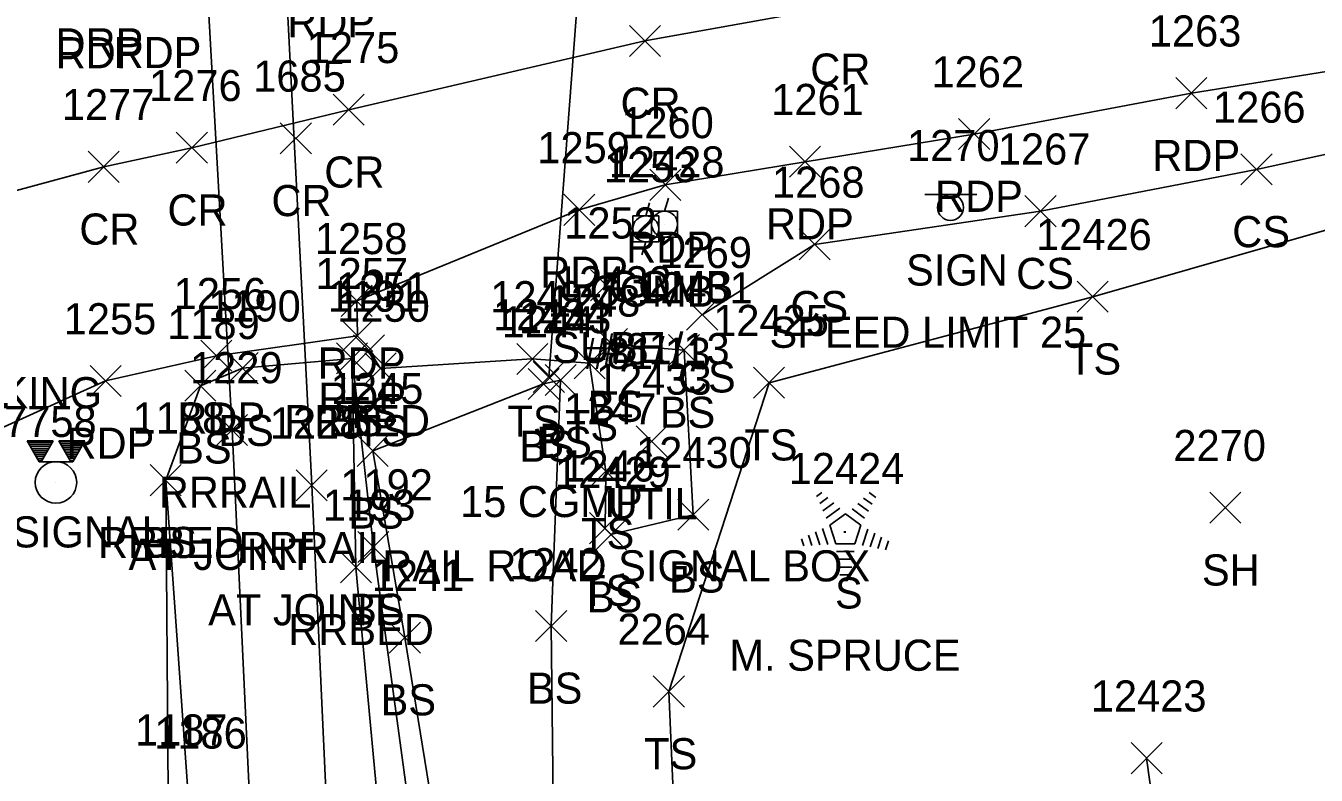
# Model space of a CAD drawing. Extents: x 1769141 to 1770817, y 735471 to 742405.
# Drawn here: x 1770150.6 to 1770233.5, y 741062.5 to 741110.6 of the extents above; entities that cross this region are included whole.
import ezdxf

# ---------------------------------------------------------------- set-up
doc = ezdxf.new("R2010")
doc.units = 0
for name, color, linetype in [('D_A', 7, 'Continuous'), ('D_C', 7, 'Continuous'), ('D_I', 7, 'Continuous'), ('D_TIC', 7, 'Continuous'), ('DCP', 7, 'Continuous'), ('L_A', 7, 'Continuous'), ('L_C', 7, 'Continuous'), ('L_I', 7, 'Continuous'), ('L_TIC', 7, 'Continuous'), ('LDEFAULT', 7, 'Continuous'), ('LELB', 7, 'Continuous'), ('LTC', 7, 'Continuous'), ('P_A', 7, 'Continuous'), ('P_I', 7, 'Continuous'), ('P_TIC', 7, 'Continuous'), ('PET', 7, 'Continuous'), ('PRC', 7, 'Continuous'), ('R_A', 7, 'Continuous'), ('R_C', 7, 'Continuous'), ('R_I', 7, 'Continuous'), ('R_TIC', 7, 'Continuous'), ('RR', 7, 'Continuous'), ('RRB', 7, 'Continuous'), ('S_A', 7, 'Continuous'), ('S_C', 7, 'Continuous'), ('S_I', 7, 'Continuous'), ('SSGN', 7, 'Continuous'), ('TCSH', 7, 'Continuous'), ('U_A', 7, 'Continuous'), ('U_C', 7, 'Continuous'), ('U_I', 7, 'Continuous'), ('U_TIC', 7, 'Continuous'), ('UDEFAULT', 7, 'Continuous'), ('UP', 7, 'Continuous')]:
    doc.layers.add(name, color=color, linetype=linetype)

msp = doc.modelspace()

# ---------------------------------------------------------------- linework, layer by layer
at = {"layer": 'D_TIC'}
for points in [[(1770183.2, 741087.048), (1770185.2, 741089.048)], [(1770185.2, 741087.048), (1770183.2, 741089.048)]]:
    msp.add_lwpolyline(points, dxfattribs=at)
at = {"layer": 'DCP'}
msp.add_lwpolyline([(1770184.2, 741088.048), (1770187.399, 741130.068)], dxfattribs=at)
at = {"layer": 'L_TIC'}
for points in [[(1770228.687, 741100.394), (1770230.687, 741102.394)], [(1770230.687, 741100.394), (1770228.687, 741102.394)], [(1770214.801, 741097.707), (1770216.801, 741099.707)], [(1770216.801, 741097.707), (1770214.801, 741099.707)], [(1770200.283, 741095.576), (1770202.283, 741097.576)], [(1770202.283, 741095.576), (1770200.283, 741097.576)], [(1770218.162, 741092.21), (1770220.162, 741094.21)], [(1770220.162, 741092.21), (1770218.162, 741094.21)], [(1770193.054, 741091.056), (1770195.054, 741093.056)], [(1770195.054, 741091.056), (1770193.054, 741093.056)], [(1770187.245, 741089.171), (1770189.245, 741091.171)], [(1770189.245, 741089.171), (1770187.245, 741091.171)], [(1770170.551, 741088.247), (1770172.551, 741090.247)], [(1770172.551, 741088.247), (1770170.551, 741090.247)], [(1770171.642, 741088.771), (1770173.642, 741090.771)], [(1770173.642, 741088.771), (1770171.642, 741090.771)], [(1770182.133, 741088.213), (1770184.133, 741090.213)], [(1770184.133, 741088.213), (1770182.133, 741090.213)], [(1770191.889, 741088.785), (1770193.889, 741090.785)], [(1770193.889, 741088.785), (1770191.889, 741090.785)], [(1770163.515, 741087.618), (1770165.515, 741089.618)], [(1770165.515, 741087.618), (1770163.515, 741089.618)], [(1770172.38, 741087.601), (1770174.38, 741089.601)], [(1770174.38, 741087.601), (1770172.38, 741089.601)], [(1770185.823, 741087.936), (1770187.823, 741089.936)], [(1770187.823, 741087.936), (1770185.823, 741089.936)], [(1770182.86, 741086.602), (1770184.86, 741088.602)], [(1770184.86, 741086.602), (1770182.86, 741088.602)], [(1770183.959, 741086.855), (1770185.959, 741088.855)], [(1770185.959, 741086.855), (1770183.959, 741088.855)], [(1770197.356, 741086.687), (1770199.356, 741088.687)], [(1770199.356, 741086.687), (1770197.356, 741088.687)], [(1770160.803, 741086.488), (1770162.803, 741088.488)], [(1770162.803, 741086.488), (1770160.803, 741088.488)], [(1770171.875, 741082.308), (1770173.875, 741084.308)], [(1770173.875, 741082.308), (1770171.875, 741084.308)], [(1770171.875, 741082.308), (1770173.875, 741084.308)], [(1770173.875, 741082.308), (1770171.875, 741084.308)], [(1770186.864, 741081), (1770188.864, 741083)], [(1770188.864, 741081), (1770186.864, 741083)], [(1770158.572, 741080.418), (1770160.572, 741082.418)], [(1770160.572, 741080.418), (1770158.572, 741082.418)], [(1770226.692, 741078.65), (1770228.692, 741080.65)], [(1770228.692, 741078.65), (1770226.692, 741080.65)], [(1770192.486, 741078.198), (1770194.486, 741080.198)], [(1770194.486, 741078.198), (1770192.486, 741080.198)], [(1770186.814, 741077.333), (1770188.814, 741079.333)], [(1770188.814, 741077.333), (1770186.814, 741079.333)], [(1770187.193, 741076.925), (1770189.193, 741078.925)], [(1770189.193, 741076.925), (1770187.193, 741078.925)], [(1770171.918, 741076.122), (1770173.918, 741078.122)], [(1770173.918, 741076.122), (1770171.918, 741078.122)], [(1770183.347, 741071.054), (1770185.347, 741073.054)], [(1770185.347, 741071.054), (1770183.347, 741073.054)], [(1770173.941, 741070.303), (1770175.941, 741072.303)], [(1770175.941, 741070.303), (1770173.941, 741072.303)], [(1770190.915, 741066.839), (1770192.915, 741068.839)], [(1770192.915, 741066.839), (1770190.915, 741068.839)], [(1770221.627, 741062.552), (1770223.627, 741064.552)], [(1770223.627, 741062.552), (1770221.627, 741064.552)]]:
    msp.add_lwpolyline(points, dxfattribs=at)
at = {"layer": 'LDEFAULT'}
msp.add_lwpolyline([(1770223.89, 741054.585), (1770222.627, 741063.552)], dxfattribs=at)
at = {"layer": 'LELB'}
for points in [[(1770243.463, 741104.407), (1770229.687, 741101.394), (1770215.801, 741098.707), (1770201.283, 741096.576), (1770194.054, 741092.056)], [(1770198.356, 741087.687), (1770219.162, 741093.21), (1770237.65, 741098.502)], [(1770187.814, 741078.333), (1770187.864, 741082), (1770186.823, 741088.936), (1770183.133, 741089.213), (1770173.38, 741088.601), (1770172.642, 741089.771)], [(1770188.193, 741077.925), (1770193.486, 741079.198), (1770192.889, 741089.785), (1770188.245, 741090.171)], [(1770181.311, 740917.449), (1770179.59, 740921.475), (1770177.118, 740921.478), (1770176.513, 740930.978), (1770171.729, 740930.79), (1770171.373, 740941.995), (1770168.363, 740945.327), (1770165.11, 740957.298), (1770164.098, 740970.155), (1770163.553, 741001.041), (1770161.742, 741032.797), (1770159.725, 741061.367), (1770159.572, 741081.418), (1770161.803, 741087.488), (1770164.515, 741088.618), (1770171.551, 741089.247), (1770172.918, 741077.122), (1770176.833, 741048.502), (1770177.259, 741011.933), (1770177.974, 741001.323)], [(1770191.558, 740906.735), (1770190.424, 740913.16), (1770188.625, 740919.349), (1770188.228, 740928.375), (1770184.924, 740957.584), (1770183.564, 740988.367), (1770184.534, 741002.508), (1770184.56, 741025.112), (1770184.692, 741042.338), (1770184.347, 741072.054), (1770184.959, 741087.855), (1770183.86, 741087.602), (1770172.875, 741083.308)], [(1770191.915, 741067.839), (1770198.356, 741087.687)], [(1770202.748, 740852.913), (1770198.081, 740870.23), (1770189.013, 740895.049), (1770187.933, 740904.335), (1770187.578, 740912.346), (1770187.376, 740919.181), (1770186.633, 740920.541), (1770186.963, 740928.353), (1770183.64, 740957.629), (1770181.485, 740987.987), (1770182.217, 741002.634), (1770183.145, 741024.654), (1770182.277, 741042.266), (1770177.798, 741053.788), (1770174.941, 741071.303), (1770172.875, 741083.308)], [(1770246.421, 740860.872), (1770241.286, 740876.805), (1770234.165, 740888.347), (1770224.288, 740902.422), (1770215.42, 740910.628), (1770206.685, 740921.814), (1770206.632, 740941.936), (1770205.486, 740949.715), (1770198.228, 740957.016), (1770197.639, 740983.28), (1770195.586, 740993.523), (1770190.462, 741017.376), (1770192.785, 741047.528), (1770191.915, 741067.839)]]:
    msp.add_lwpolyline(points, dxfattribs=at)
at = {"layer": 'LTC'}
for p, q in [((1770201.402, 741080.38), (1770201.756, 741080.638)), ((1770201.611, 741079.915), (1770202.141, 741080.299)), ((1770204.429, 741080.272), (1770204.979, 741079.873)), ((1770204.8, 741080.621), (1770205.219, 741080.316)), ((1770201.821, 741079.449), (1770202.525, 741079.96)), ((1770202.031, 741078.983), (1770202.909, 741079.621)), ((1770203.687, 741079.576), (1770204.496, 741078.987)), ((1770204.058, 741079.924), (1770204.737, 741079.43)), ((1770202.255, 741078.528), (1770203.267, 741079.263)), ((1770203.267, 741079.263), (1770204.264, 741078.538)), ((1770200.89, 741077.876), (1770201.101, 741077.224)), ((1770201.345, 741078.093), (1770201.616, 741077.257)), ((1770201.801, 741078.309), (1770202.131, 741077.29)), ((1770202.255, 741078.528), (1770202.642, 741077.335)), ((1770204.264, 741078.538), (1770203.873, 741077.335)), ((1770204.701, 741078.267), (1770204.364, 741077.227)), ((1770205.146, 741078.016), (1770204.859, 741077.132)), ((1770205.591, 741077.766), (1770205.354, 741077.037)), ((1770200.434, 741077.659), (1770200.586, 741077.191)), ((1770203.873, 741077.335), (1770202.642, 741077.335)), ((1770206.035, 741077.516), (1770205.848, 741076.942)), ((1770203.834, 741076.835), (1770202.69, 741076.835)), ((1770203.751, 741076.335), (1770202.762, 741076.335)), ((1770203.667, 741075.835), (1770202.835, 741075.835)), ((1770203.583, 741075.335), (1770202.908, 741075.335))]:
    msp.add_line(p, q, dxfattribs=at)
at = {"layer": 'P_TIC'}
for points in [[(1770189.375, 741108.654), (1770191.375, 741110.654)], [(1770191.375, 741108.654), (1770189.375, 741110.654)], [(1770224.504, 741105.293), (1770226.504, 741107.293)], [(1770226.504, 741105.293), (1770224.504, 741107.293)], [(1770170.332, 741104.227), (1770172.332, 741106.227)], [(1770172.332, 741104.227), (1770170.332, 741106.227)], [(1770166.935, 741102.391), (1770168.935, 741104.391)], [(1770168.935, 741102.391), (1770166.935, 741104.391)], [(1770210.537, 741102.665), (1770212.537, 741104.665)], [(1770212.537, 741102.665), (1770210.537, 741104.665)], [(1770160.251, 741101.786), (1770162.251, 741103.786)], [(1770162.251, 741101.786), (1770160.251, 741103.786)], [(1770199.669, 741100.89), (1770201.669, 741102.89)], [(1770201.669, 741100.89), (1770199.669, 741102.89)], [(1770154.587, 741100.56), (1770156.587, 741102.56)], [(1770156.587, 741100.56), (1770154.587, 741102.56)], [(1770190.681, 741099.4), (1770192.681, 741101.4)], [(1770192.681, 741099.4), (1770190.681, 741101.4)], [(1770185.159, 741097.793), (1770187.159, 741099.793)], [(1770187.159, 741097.793), (1770185.159, 741099.793)], [(1770170.852, 741091.948), (1770172.852, 741093.948)], [(1770172.852, 741091.948), (1770170.852, 741093.948)], [(1770170.891, 741089.698), (1770172.891, 741091.698)], [(1770172.891, 741089.698), (1770170.891, 741091.698)], [(1770161.831, 741088.417), (1770163.831, 741090.417)], [(1770163.831, 741088.417), (1770161.831, 741090.417)], [(1770154.707, 741086.796), (1770156.707, 741088.796)], [(1770156.707, 741086.796), (1770154.707, 741088.796)]]:
    msp.add_lwpolyline(points, dxfattribs=at)
at = {"layer": 'PET'}
msp.add_lwpolyline([(1770147.313, 741084.024), (1770155.707, 741087.796), (1770162.831, 741089.417), (1770171.891, 741090.698), (1770171.852, 741092.948), (1770186.159, 741098.793), (1770191.681, 741100.4), (1770200.669, 741101.89), (1770211.537, 741103.665), (1770225.504, 741106.293), (1770242.459, 741109.014)], dxfattribs=at)
at = {"layer": 'PRC'}
msp.add_lwpolyline([(1770240.032, 741122.25), (1770223.985, 741117.036), (1770202.573, 741111.843), (1770190.375, 741109.654), (1770171.332, 741105.227), (1770161.251, 741102.786), (1770155.587, 741101.56), (1770143.323, 741098.229)], dxfattribs=at)
at = {"layer": 'R_TIC'}
for points in [[(1770170.551, 741088.247), (1770172.551, 741090.247)], [(1770172.551, 741088.247), (1770170.551, 741090.247)], [(1770162.837, 741083.651), (1770164.837, 741085.651)], [(1770164.837, 741083.651), (1770162.837, 741085.651)], [(1770158.572, 741080.418), (1770160.572, 741082.418)], [(1770160.572, 741080.418), (1770158.572, 741082.418)], [(1770167.957, 741080.093), (1770169.957, 741082.093)], [(1770169.957, 741080.093), (1770167.957, 741082.093)], [(1770170.802, 741074.818), (1770172.802, 741076.818)], [(1770172.802, 741074.818), (1770170.802, 741076.818)]]:
    msp.add_lwpolyline(points, dxfattribs=at)
at = {"layer": 'RR'}
for points in [[(1770197.753, 740390.494), (1770195.855, 740429.491), (1770193.917, 740468.481), (1770191.987, 740507.454), (1770190.016, 740546.417), (1770188.175, 740585.45), (1770186.345, 740624.52), (1770184.351, 740663.534), (1770182.414, 740702.58), (1770181.022, 740730.449), (1770179.246, 740766.268), (1770177.157, 740810.299), (1770173.744, 740877.111), (1770171.322, 740927.707), (1770169.445, 740967.981), (1770167.613, 741006.359), (1770166.537, 741027.4), (1770165.653, 741046.208), (1770163.837, 741084.651), (1770161.662, 741123.764), (1770160.41, 741153.194), (1770158.416, 741192.158), (1770156.873, 741228.018)], [(1770203.658, 740370.746), (1770201.768, 740409.672), (1770199.783, 740448.72), (1770197.896, 740487.783), (1770195.957, 740526.733), (1770194.091, 740565.766), (1770192.139, 740604.842), (1770190.284, 740643.849), (1770188.287, 740682.87), (1770186.409, 740721.831), (1770184.146, 740769.997), (1770182.623, 740801.289), (1770179.628, 740862.115), (1770176.856, 740918.905), (1770174.1, 740971.708), (1770172.224, 741013.506), (1770171.361, 741030.469), (1770170.329, 741051.221), (1770168.957, 741081.093), (1770166.986, 741119.982), (1770165.661, 741147.286), (1770164.69, 741163.317), (1770164.281, 741173.164), (1770162.436, 741212.293)]]:
    msp.add_lwpolyline(points, dxfattribs=at)
at = {"layer": 'RRB'}
for points in [[(1770171.551, 741089.247), (1770171.802, 741075.818), (1770174.339, 741048.396), (1770176.174, 741011.52), (1770177.974, 741001.323), (1770177.958, 740979.099), (1770179.842, 740948.528), (1770182.395, 740920.735)], [(1770168.363, 740945.327), (1770167.014, 740957.66), (1770166.65, 740970.662), (1770165.111, 741000.961), (1770162.752, 741033.641), (1770161.012, 741061.171), (1770159.572, 741081.418)]]:
    msp.add_lwpolyline(points, dxfattribs=at)
at = {"layer": 'SSGN'}
for p, q in [((1770208.375, 741099.783), (1770211.708, 741099.783)), ((1770210.022, 741098.949), (1770210.022, 741098.949))]:
    msp.add_line(p, q, dxfattribs=at)
msp.add_circle((1770210.022, 741098.949), 0.833, dxfattribs=at)
at = {"layer": 'TCSH'}
for p, q in [((1770152.332, 741083.941), (1770150.665, 741083.941)), ((1770150.665, 741083.941), (1770151.435, 741082.608)), ((1770151.562, 741082.608), (1770152.332, 741083.941)), ((1770154.367, 741083.941), (1770152.7, 741083.941)), ((1770152.7, 741083.941), (1770153.47, 741082.608)), ((1770153.597, 741082.608), (1770154.367, 741083.941)), ((1770153.597, 741082.608), (1770151.435, 741082.608)), ((1770152.516, 741081.275), (1770152.516, 741081.275))]:
    msp.add_line(p, q, dxfattribs=at)
for points in [[(1770150.71, 741083.865), (1770152.288, 741083.865)], [(1770150.787, 741083.732), (1770152.211, 741083.732)], [(1770150.864, 741083.598), (1770152.134, 741083.598)], [(1770152.728, 741083.893), (1770154.339, 741083.893)], [(1770152.805, 741083.76), (1770154.262, 741083.76)], [(1770152.882, 741083.627), (1770154.185, 741083.627)], [(1770150.941, 741083.465), (1770152.057, 741083.465)], [(1770151.018, 741083.332), (1770151.98, 741083.332)], [(1770151.095, 741083.198), (1770151.903, 741083.198)], [(1770151.172, 741083.065), (1770151.826, 741083.065)], [(1770151.248, 741082.932), (1770151.749, 741082.932)], [(1770151.325, 741082.798), (1770151.672, 741082.798)], [(1770152.959, 741083.493), (1770154.108, 741083.493)], [(1770153.036, 741083.36), (1770154.031, 741083.36)], [(1770153.113, 741083.227), (1770153.954, 741083.227)], [(1770153.19, 741083.093), (1770153.877, 741083.093)], [(1770153.267, 741082.96), (1770153.8, 741082.96)], [(1770153.344, 741082.827), (1770153.723, 741082.827)], [(1770151.402, 741082.665), (1770151.595, 741082.665)], [(1770153.421, 741082.693), (1770153.646, 741082.693)]]:
    msp.add_lwpolyline(points, dxfattribs=at)
msp.add_circle((1770152.516, 741081.275), 1.333, dxfattribs=at)
at = {"layer": 'U_TIC'}
for points in [[(1770186.883, 741092.951), (1770188.883, 741094.951)], [(1770188.883, 741092.951), (1770186.883, 741094.951)]]:
    msp.add_lwpolyline(points, dxfattribs=at)
at = {"layer": 'UDEFAULT'}
for points in [[(1770189.816, 741082.914), (1770191.816, 741084.914)], [(1770191.816, 741082.914), (1770189.816, 741084.914)]]:
    msp.add_lwpolyline(points, dxfattribs=at)
at = {"layer": 'UP'}
for p, q in [((1770191.891, 741099.54), (1770191.641, 741098.707)), ((1770190.678, 741099.237), (1770190.428, 741098.404)), ((1770190.807, 741097.04), (1770190.807, 741098.707)), ((1770190.807, 741098.707), (1770192.474, 741098.707)), ((1770192.474, 741098.707), (1770192.474, 741097.04)), ((1770189.595, 741096.737), (1770189.595, 741098.404)), ((1770189.595, 741098.404), (1770191.262, 741098.404)), ((1770191.262, 741098.404), (1770191.262, 741096.737)), ((1770191.641, 741097.874), (1770191.641, 741097.874)), ((1770190.428, 741097.57), (1770190.428, 741097.57)), ((1770192.474, 741097.04), (1770190.807, 741097.04)), ((1770191.391, 741096.207), (1770191.641, 741097.04)), ((1770191.262, 741096.737), (1770189.595, 741096.737)), ((1770190.178, 741095.904), (1770190.428, 741096.737))]:
    msp.add_line(p, q, dxfattribs=at)
for centre in [(1770191.641, 741097.874), (1770190.428, 741097.57)]:
    msp.add_circle(centre, 0.833, dxfattribs=at)

# ---------------------------------------------------------------- texts
at = {"layer": 'D_A'}
msp.add_text('P', height=2, dxfattribs=at).set_placement((1770183.578, 741083.048))
at = {"layer": 'D_C'}
msp.add_text('15 CGMP', height=2, dxfattribs=at).set_placement((1770178.492, 741079.048))
at = {"layer": 'D_I'}
msp.add_text('12434', height=2, dxfattribs=at).set_placement((1770180.61, 741091.048))
at = {"layer": 'L_A'}
for s, p in [('CS', (1770228.128, 741096.394)), ('CS', (1770214.242, 741093.707)), ('CS', (1770199.724, 741091.576)), ('TS', (1770217.572, 741088.21)), ('CS', (1770192.495, 741087.056)), ('BS', (1770186.686, 741085.171)), ('BS', (1770169.992, 741084.247)), ('TS', (1770171.051, 741084.771)), ('TS', (1770181.542, 741084.213)), ('BS', (1770191.33, 741084.785)), ('BS', (1770162.956, 741083.618)), ('TS', (1770171.789, 741083.601)), ('TS', (1770185.233, 741083.936)), ('BS', (1770160.244, 741082.488)), ('BS', (1770182.301, 741082.602)), ('BS', (1770183.4, 741082.855)), ('TS', (1770196.765, 741082.687)), ('BS', (1770171.316, 741078.308)), ('BS', (1770171.316, 741078.308)), ('TS', (1770186.273, 741077)), ('BS', (1770158.013, 741076.418)), ('BS', (1770191.927, 741074.198)), ('SH', (1770226.18, 741074.65)), ('TS', (1770186.223, 741073.333)), ('BS', (1770186.634, 741072.925)), ('S', (1770202.593, 741073.172)), ('BS', (1770171.359, 741072.122)), ('BS', (1770182.788, 741067.054)), ('BS', (1770173.382, 741066.303)), ('TS', (1770190.324, 741062.839))]:
    msp.add_text(s, height=2, dxfattribs=at).set_placement(p)
at = {"layer": 'L_C'}
msp.add_text('M. SPRUCE', height=2, dxfattribs=at).set_placement((1770195.805, 741069.172))
at = {"layer": 'L_I'}
for s, p in [('1266', (1770226.892, 741104.394)), ('1267', (1770213.061, 741101.707)), ('1268', (1770198.543, 741099.576)), ('12426', (1770215.517, 741096.21)), ('1269', (1770191.306, 741095.056)), ('12432', (1770184.655, 741093.171)), ('1251', (1770170.516, 741092.771)), ('12431', (1770189.866, 741092.785)), ('1190', (1770162.303, 741091.618)), ('1191', (1770169.992, 741092.247)), ('1250', (1770170.6, 741091.601)), ('1249', (1770180.432, 741092.213)), ('1248', (1770184.13, 741091.936)), ('1243', (1770182.267, 741090.855)), ('12425', (1770194.765, 741090.687)), ('1189', (1770159.669, 741090.488)), ('1244', (1770181.167, 741090.602)), ('1245', (1770170.183, 741086.308)), ('1245', (1770170.183, 741086.308)), ('1247', (1770185.171, 741085)), ('1188', (1770157.447, 741084.418)), ('2270', (1770224.345, 741082.65)), ('12430', (1770189.809, 741082.198)), ('12429', (1770184.595, 741080.925)), ('1246', (1770185.066, 741081.333)), ('12424', (1770199.616, 741081.172)), ('1192', (1770170.793, 741080.122)), ('1242', (1770181.654, 741075.054)), ('1241', (1770172.815, 741074.303)), ('2264', (1770188.608, 741070.839)), ('12423', (1770219.037, 741066.552)), ('1187', (1770157.599, 741064.367))]:
    msp.add_text(s, height=2, dxfattribs=at).set_placement(p)
at = {"layer": 'LTC'}
msp.add_text('.', height=1.037, rotation=270, dxfattribs=at).set_placement((1770203.149, 741078.276))
at = {"layer": 'P_A'}
for s, p in [('RDP', (1770167.386, 741109.873)), ('RDP', (1770152.499, 741107.895)), ('RDP', (1770156.22, 741107.907)), ('CR', (1770201.006, 741106.843)), ('CR', (1770188.808, 741104.654)), ('RDP', (1770222.993, 741101.293)), ('CR', (1770169.765, 741100.227)), ('CR', (1770166.368, 741098.391)), ('RDP', (1770209.026, 741098.665)), ('CR', (1770159.685, 741097.786)), ('CR', (1770154.02, 741096.56)), ('RDP', (1770198.157, 741096.89)), ('RDP', (1770189.169, 741095.4)), ('RDP', (1770183.647, 741093.793)), ('RDP', (1770169.34, 741087.948)), ('RDP', (1770169.38, 741085.698)), ('RDP', (1770160.319, 741084.417)), ('RDP', (1770153.195, 741082.796))]:
    msp.add_text(s, height=2, dxfattribs=at).set_placement(p)
at = {"layer": 'P_I'}
for s, p in [('1263', (1770222.764, 741109.293)), ('1275', (1770168.639, 741108.227)), ('1262', (1770208.797, 741106.665)), ('1276', (1770158.504, 741105.786)), ('1685', (1770165.195, 741106.391)), ('1261', (1770198.496, 741104.89)), ('1277', (1770152.894, 741104.56)), ('1260', (1770188.854, 741103.4)), ('1259', (1770183.458, 741101.793)), ('1258', (1770169.159, 741095.948)), ('1257', (1770169.199, 741093.698)), ('1256', (1770160.083, 741092.417)), ('1255', (1770153.014, 741090.796))]:
    msp.add_text(s, height=2, dxfattribs=at).set_placement(p)
at = {"layer": 'R_A'}
for s, p in [('DRP', (1770152.486, 741108.466)), ('RRBED', (1770167.197, 741084.247)), ('RRRAIL', (1770159.128, 741079.651)), ('RRSIGNAL', (1770145.843, 741077.097)), ('RRBED', (1770155.218, 741076.418)), ('RRRAIL', (1770164.249, 741076.093)), ('RRBED', (1770167.448, 741070.818))]:
    msp.add_text(s, height=2, dxfattribs=at).set_placement(p)
at = {"layer": 'R_C'}
for p in [(1770157.183, 741075.651), (1770162.304, 741072.093)]:
    msp.add_text('AT JOINT', height=2, dxfattribs=at).set_placement(p)
at = {"layer": 'R_I'}
for s, p in [('1191', (1770169.992, 741092.247)), ('1229', (1770161.136, 741087.651)), ('7758', (1770149.181, 741084.197)), ('1188', (1770157.447, 741084.418)), ('1228', (1770166.264, 741084.093)), ('1193', (1770169.677, 741078.818)), ('1186', (1770158.832, 741064.171))]:
    msp.add_text(s, height=2, dxfattribs=at).set_placement(p)
at = {"layer": 'S_A'}
for s, p in [('SIGN', (1770207.16, 741093.929)), ('PAVEMARKING', (1770135.86, 741086.045))]:
    msp.add_text(s, height=2, dxfattribs=at).set_placement(p)
at = {"layer": 'S_C'}
msp.add_text('SPEED LIMIT 25', height=2, dxfattribs=at).set_placement((1770198.381, 741089.929))
at = {"layer": 'S_I'}
msp.add_text('1270', height=2, dxfattribs=at).set_placement((1770207.223, 741101.929))
at = {"layer": 'U_A'}
for s, p in [('COMB', (1770186.814, 741092.57)), ('COMB', (1770188.027, 741092.874)), ('SUBE', (1770184.418, 741088.951)), ('UTIL', (1770187.982, 741078.914))]:
    msp.add_text(s, height=2, dxfattribs=at).set_placement(p)
at = {"layer": 'U_C'}
for s, p in [('#81/13', (1770186.429, 741088.57)), ('#81/13', (1770187.641, 741088.874)), ('RAIL ROAD SIGNAL BOX', (1770173.494, 741074.914))]:
    msp.add_text(s, height=2, dxfattribs=at).set_placement(p)
at = {"layer": 'U_I'}
for s, p in [('12428', (1770188.05, 741100.874)), ('1253', (1770187.735, 741100.57)), ('1252', (1770185.19, 741096.951)), ('12433', (1770187.226, 741086.914))]:
    msp.add_text(s, height=2, dxfattribs=at).set_placement(p)

doc.saveas('drawing.dxf')
